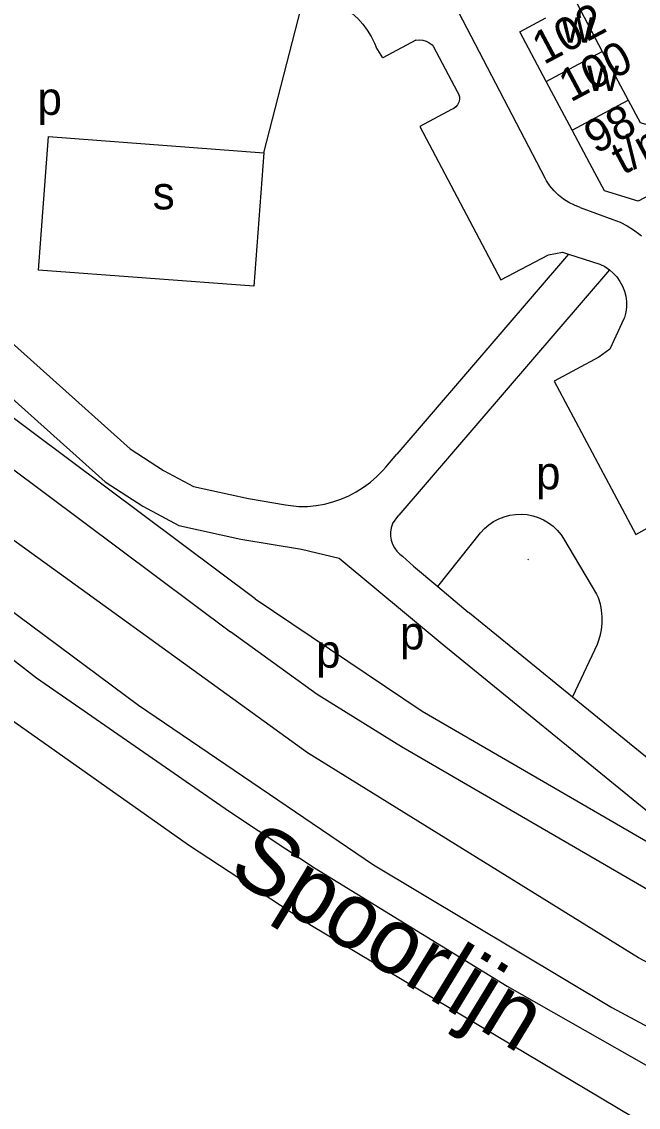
# Model space of a CAD drawing. Extents: x 159902 to 161769, y 383692 to 384875.
# Drawn here: x 160524 to 160598.8, y 383771.4 to 383903 of the extents above; entities that cross this region are included whole.
import ezdxf

# ---------------------------------------------------------------- set-up
doc = ezdxf.new("R2010")
doc.units = 0
for name, color, linetype in [('BLT_Basislijn', 7, 'Continuous'), ('BLT_Bebouwing', 7, 'Continuous'), ('BLT_Centroide', 7, 'Continuous'), ('BLT_Huisnummer', 7, 'Continuous'), ('BLT_Huisnummer_ tussenligend', 7, 'Continuous'), ('BLT_Huisnummer_reeks', 7, 'Continuous'), ('BLT_Onderverdeling_panden', 7, 'Continuous'), ('BLT_Spoorlijn', 7, 'Continuous'), ('BLT_Vlakafsluiter', 7, 'Continuous'), ('BLT_Waternaam_spoorwegen', 7, 'Continuous')]:
    doc.layers.add(name, color=color, linetype=linetype)

msp = doc.modelspace()

# ---------------------------------------------------------------- linework, layer by layer
at = {"layer": 'BLT_Basislijn'}
for p, q in [((160573.94, 383900.07), (160576.87, 383894.55)), ((160576.15, 383892.37), (160572.31, 383890.3)), ((160572.31, 383890.3), (160582.16, 383871.71)), ((160591.79, 383880.5), (160595.73, 383879.04)), ((160590.37, 383874.84), (160569.52, 383850.58)), ((160582.16, 383871.71), (160587.95, 383874.76)), ((160590.37, 383874.84), (160594.17, 383873.62)), ((160595.33, 383872.94), (160569.77, 383843.19)), ((160594.05, 383862.32), (160588.63, 383859.42)), ((160568.19, 383848.99), (160569.52, 383850.58)), ((160556.04, 383844.44), (160557.66, 383844.21)), ((160569, 383842.11), (160569.77, 383843.19)), ((160574.49, 383834.52), (160579.69, 383841.02)), ((160589.76, 383840.34), (160593.75, 383833.59)), ((160571.55, 383836.97), (160570.21, 383838.22)), ((160585.43, 383837.82), (160585.49, 383837.74)), ((160571.55, 383836.97), (160574.49, 383834.52)), ((160593.75, 383833.59), (160593.94, 383833.17)), ((160552.35, 383833.03), (160572.6, 383819.39)), ((160578.33, 383831.32), (160586.86, 383824.38)), ((160593.82, 383827.47), (160590.85, 383821.13)), ((160586.86, 383824.38), (160590.85, 383821.13))]:
    msp.add_line(p, q, dxfattribs=at)
for points in [[(160332.83, 384037.54), (160387.41, 383973.03), (160409.45, 383948.29), (160442.61, 383913.47), (160476.86, 383880.31), (160497.51, 383864), (160513.41, 383855.86), (160549.35, 383829.03)], [(160552.35, 383833.03), (160516.07, 383860.12), (160500.23, 383868.23), (160480.16, 383884.08), (160446.09, 383917.07)], [(160587.52, 383884.04), (160575.54, 383907.06), (160574.98, 383907.97)], [(160558.36, 383906.48), (160559.26, 383906.36), (160560.15, 383906.15), (160561.01, 383905.87), (160561.85, 383905.51), (160562.65, 383905.09), (160563.42, 383904.59), (160564.13, 383904.03), (160564.8, 383903.4), (160565.4, 383902.72), (160565.95, 383901.99), (160566.43, 383901.22), (160566.83, 383900.41), (160567.03, 383899.93)], [(160571.85, 383900.78), (160567.85, 383898.64), (160567.03, 383899.93)], [(160571.85, 383900.78), (160572.27, 383900.82), (160572.69, 383900.78), (160573.09, 383900.66), (160573.47, 383900.47), (160573.8, 383900.22), (160573.94, 383900.07)], [(160576.87, 383894.55), (160577.03, 383894.26), (160577.12, 383893.93), (160577.12, 383893.59), (160577.05, 383893.26), (160576.91, 383892.96), (160576.69, 383892.7), (160576.43, 383892.49), (160576.15, 383892.37)], [(160553.4, 383887.1), (160552.19, 383870.94), (160526.06, 383872.9), (160527.27, 383889.08), (160553.4, 383887.1)], [(160499.71, 383884.73), (160537.18, 383851.2), (160541.24, 383848.59), (160544.85, 383846.65), (160551.53, 383845.19), (160556.04, 383844.44)], [(160591.79, 383880.5), (160591.08, 383880.76), (160590.39, 383881.1), (160589.75, 383881.51), (160589.15, 383881.98), (160588.6, 383882.51), (160588.11, 383883.1), (160587.69, 383883.74), (160587.52, 383884.04)], [(160494.74, 383882.47), (160534.14, 383847.21), (160538.7, 383844.28), (160543.1, 383841.91), (160550.59, 383840.28), (160557.96, 383839.05), (160562.54, 383837.97), (160575.03, 383827.56), (160599.76, 383807.45), (160612.28, 383798.99), (160628.85, 383790.24)], [(160595.73, 383879.04), (160596.61, 383878.69), (160597.46, 383878.27), (160598.26, 383877.78), (160599.03, 383877.22), (160599.22, 383877.05)], [(160587.95, 383874.76), (160589.62, 383875.08), (160590.37, 383874.84)], [(160594.17, 383873.62), (160594.75, 383873.33), (160595.33, 383872.94)], [(160595.33, 383872.94), (160595.79, 383872.54), (160596.23, 383872.06), (160596.6, 383871.53), (160596.91, 383870.96), (160597.14, 383870.35), (160597.3, 383869.72), (160597.38, 383869.07), (160597.38, 383868.42), (160597.3, 383867.78), (160597.14, 383867.15), (160597.08, 383866.97)], [(160597.08, 383866.97), (160595.38, 383863.32), (160594.05, 383862.32)], [(160588.63, 383859.42), (160598.52, 383840.83), (160602.38, 383842.97)], [(160557.66, 383844.21), (160558.7, 383844.24), (160559.73, 383844.34), (160560.75, 383844.52), (160561.76, 383844.78), (160562.74, 383845.11), (160563.69, 383845.52), (160564.61, 383846), (160565.49, 383846.55), (160566.32, 383847.17), (160567.11, 383847.85), (160567.83, 383848.59), (160568.19, 383848.99)], [(160579.69, 383841.02), (160580.17, 383841.54), (160580.7, 383842), (160581.27, 383842.4), (160581.89, 383842.73), (160582.55, 383842.99), (160583.23, 383843.17), (160583.92, 383843.27), (160584.62, 383843.3), (160585.33, 383843.24), (160586.02, 383843.11), (160586.68, 383842.9), (160587.33, 383842.61), (160587.93, 383842.25), (160588.49, 383841.83), (160589, 383841.34), (160589.45, 383840.8), (160589.76, 383840.34)], [(160569, 383842.11), (160568.84, 383841.63), (160568.76, 383841.13), (160568.76, 383840.63), (160568.84, 383840.14), (160569, 383839.66), (160569.23, 383839.21), (160569.53, 383838.81), (160569.89, 383838.46), (160570.21, 383838.22)], [(160574.49, 383834.52), (160578.2, 383831.42), (160578.33, 383831.32)], [(160593.94, 383833.17), (160594.18, 383832.41), (160594.33, 383831.64), (160594.41, 383830.85), (160594.41, 383830.05), (160594.33, 383829.26), (160594.16, 383828.49), (160593.93, 383827.73), (160593.82, 383827.47)], [(160685.49, 383755.81), (160663.23, 383765.09), (160640.11, 383776.07), (160615.32, 383788.84), (160570.09, 383815.07), (160559.86, 383821.42), (160549.35, 383829.03)], [(160590.85, 383821.13), (160602.74, 383811.47), (160614.85, 383803.29), (160630.92, 383794.79)], [(160572.6, 383819.39), (160617.72, 383793.23), (160642.4, 383780.51)]]:
    msp.add_lwpolyline(points, dxfattribs=at)
at = {"layer": 'BLT_Bebouwing'}
for p, q in [((160591.39, 383905.17), (160594.46, 383899.4)), ((160594.46, 383899.4), (160597.6, 383893.5)), ((160590.79, 383889.87), (160587.65, 383895.78)), ((160592.95, 383885.83), (160590.79, 383889.87))]:
    msp.add_line(p, q, dxfattribs=at)
for points in [[(160587.65, 383895.78), (160584.45, 383901.79), (160587.62, 383903.48)], [(160597.6, 383893.5), (160599.05, 383890.78), (160599.71, 383890.58), (160604.65, 383893.21)], [(160601.39, 383882.65), (160598.81, 383881.27), (160594.71, 383882.52), (160592.95, 383885.83)]]:
    msp.add_lwpolyline(points, dxfattribs=at)
at = {"layer": 'BLT_Onderverdeling_panden'}
for p, q in [((160587.65, 383895.78), (160594.46, 383899.4)), ((160590.79, 383889.87), (160597.6, 383893.5))]:
    msp.add_line(p, q, dxfattribs=at)
at = {"layer": 'BLT_Spoorlijn'}
for points in [[(160470.4, 383874.31), (160500.05, 383848.69), (160513.86, 383838.19), (160538.17, 383820.13), (160566.71, 383800.78)], [(160470.21, 383868.97), (160501.15, 383842.61), (160525.83, 383823.45), (160549.21, 383807.23), (160559.53, 383800.41)], [(160793.13, 383713.32), (160766.04, 383720.12), (160726.94, 383731.96), (160686.31, 383747.06), (160640.98, 383767.11), (160598.87, 383789.48), (160558.68, 383814.33), (160516.13, 383845.06)], [(160498.71, 383836.91), (160517.36, 383822.16), (160544.24, 383803.18), (160559.16, 383793.41)], [(160566.71, 383800.78), (160595.62, 383783.46), (160626.93, 383766.69), (160664.31, 383749), (160682.91, 383741.08)], [(160559.53, 383800.41), (160582.92, 383786.04), (160609.25, 383771.11), (160628.77, 383761.16), (160650.68, 383750.29), (160671.86, 383741.08), (160684.94, 383735.73)], [(160559.16, 383793.41), (160601.88, 383767.98), (160630.43, 383753.24), (160651.05, 383743.29), (160670.57, 383735.18), (160683.46, 383730.02)]]:
    msp.add_lwpolyline(points, dxfattribs=at)
at = {"layer": 'BLT_Vlakafsluiter'}
msp.add_line((160553.4, 383887.1), (160558.36, 383906.48), dxfattribs=at)

# ---------------------------------------------------------------- texts
at = {"layer": 'BLT_Centroide'}
for s, p in [('w', (160589.52, 383900.47)), ('w', (160592.62, 383894.62)), ('p', (160525.93, 383891.72)), ('s', (160539.91, 383880.26)), ('p', (160586.41, 383846.3)), ('p', (160569.91, 383826.89)), ('p', (160559.74, 383824.67))]:
    msp.add_text(s, height=4, dxfattribs=at).set_placement(p)
at = {"layer": 'BLT_Huisnummer'}
msp.add_text('102', height=4, rotation=28.0463, dxfattribs=at).set_placement((160587.36, 383897.75))
at = {"layer": 'BLT_Huisnummer_ tussenligend'}
msp.add_text('100', height=4, rotation=28.0428, dxfattribs=at).set_placement((160590.59, 383893.19))
at = {"layer": 'BLT_Huisnummer_reeks'}
for s, rotation, p in [('98', 28.0428, (160593.65, 383886.91)), ('t/m', 28.0427, (160596.96, 383884.38))]:
    msp.add_text(s, height=4, rotation=rotation, dxfattribs=at).set_placement(p)
at = {"layer": 'BLT_Waternaam_spoorwegen'}
msp.add_text('Spoorlijn', height=8, rotation=328.5774, dxfattribs=at).set_placement((160548.81, 383799.54))

doc.saveas('drawing.dxf')
